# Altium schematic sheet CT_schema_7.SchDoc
size 278 x 170 mm
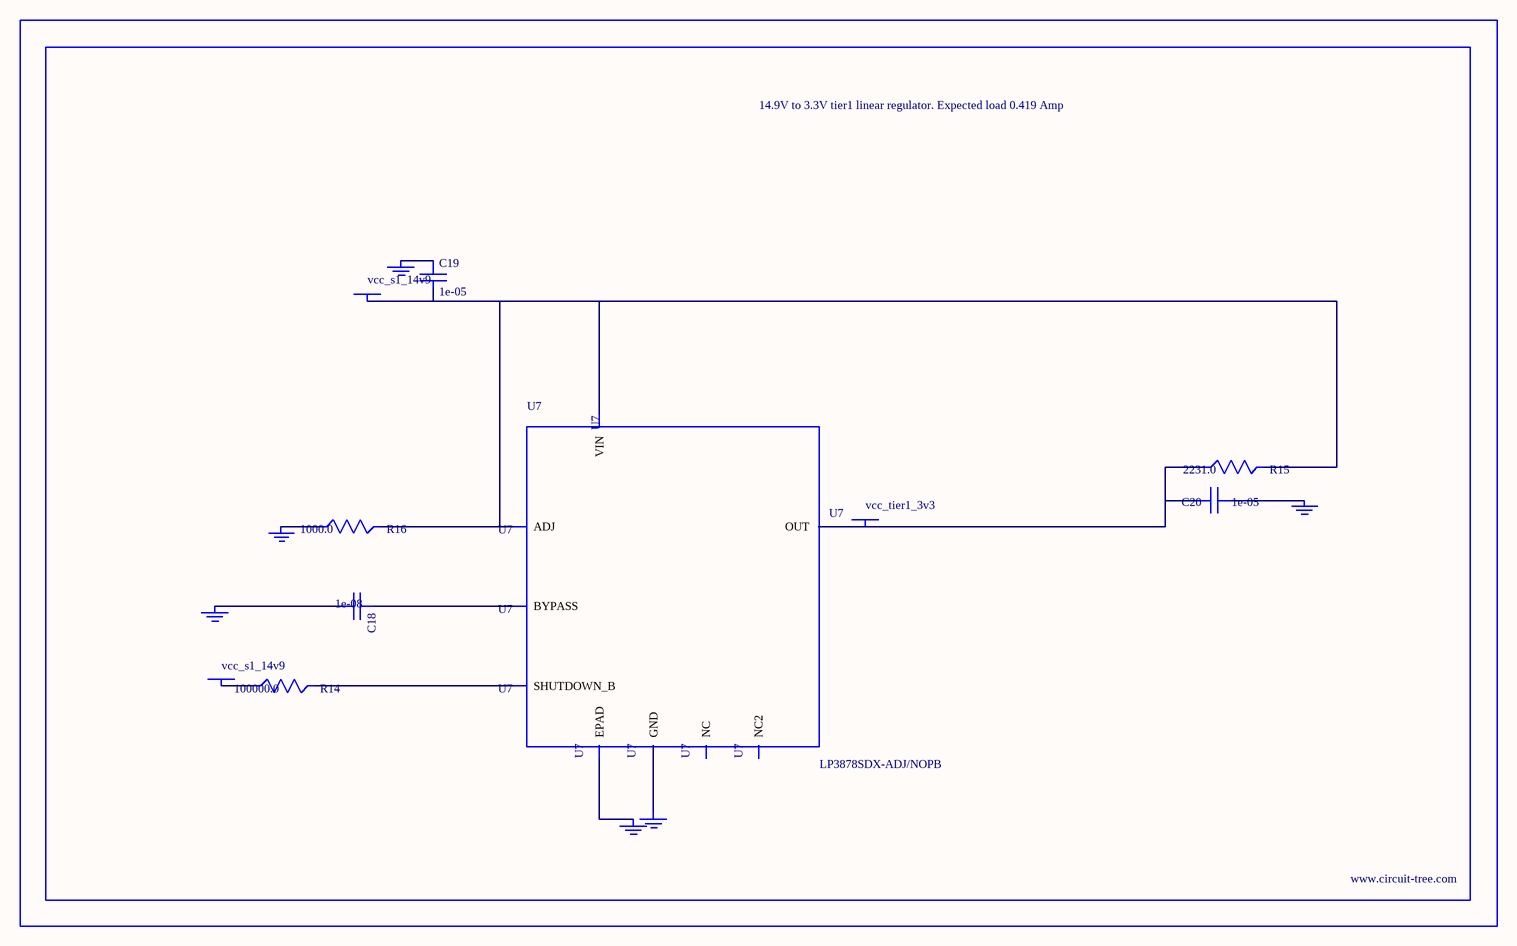
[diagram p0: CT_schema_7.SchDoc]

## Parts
BORDER6  (no value)
C18  1e-08  [C0402]
C19  1e-05  [C1210]
C20  1e-05  [C1210]
GND_INSTANCE_6_0  (no value)
GND_INSTANCE_6_1  (no value)
GND_INSTANCE_6_2  (no value)
GND_INSTANCE_6_3  (no value)
GND_INSTANCE_6_4  (no value)
GND_INSTANCE_6_5  (no value)
POWER_INSTANCE_6_0  vcc_s1_14v9
POWER_INSTANCE_6_1  vcc_s1_14v9
POWER_INSTANCE_6_2  vcc_tier1_3v3
R14  100000.0  [R0603]
R15  2231.0  [R0603]
R16  1000.0  [R0603]
U7  LP3878SDX-ADJ/NOPB  [WSON-8]

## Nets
NetC18_1: C18.1 U7.1(BYPASS)
NetC18_2: C18.2 GND_INSTANCE_6_0.0(GND)
NetC19_1: C19.1 GND_INSTANCE_6_1.0(GND)
NetC19_2: C19.2 POWER_INSTANCE_6_0.0(PWR) R15.2 R16.2 U7.4(VIN) U7.6(ADJ)
NetC20_1: C20.1 GND_INSTANCE_6_2.0(GND)
NetC20_2: C20.2 POWER_INSTANCE_6_2.0(PWR) R15.1 U7.5(OUT)
NetGND_INSTANCE_6_3_0: GND_INSTANCE_6_3.0(GND) R16.1
NetGND_INSTANCE_6_4_0: GND_INSTANCE_6_4.0(GND) U7.PAD(EPAD)
NetGND_INSTANCE_6_5_0: GND_INSTANCE_6_5.0(GND) U7.3(GND)
NetPOWER_INSTANCE_6_1_0: POWER_INSTANCE_6_1.0(PWR) R14.1
NetR14_2: R14.2 U7.8(SHUTDOWN_B)

Not connected (* = marked no-connect by the designer): U7 2(NC) 7(NC2)

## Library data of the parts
BORDER6 = BORDER_PAGE6
C18 = C0402C103K3RAC
C19 = C1210C106K5PACTU
C20 = GRM32DR61E106MA12L
GND_INSTANCE_6_0-GND_INSTANCE_6_5 = GND
POWER_INSTANCE_6_0-POWER_INSTANCE_6_2 = PWR
R14 = RC0603JR-07100KL
R15 = R15
R16 = RC0603JR-071KL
